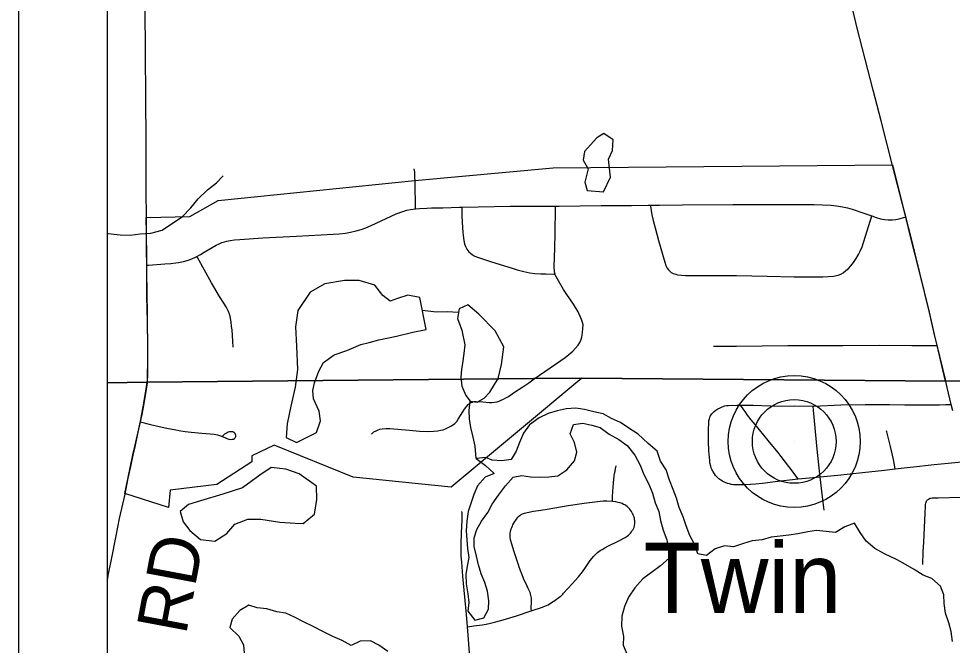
# Model space of a CAD drawing. Extents: x 0 to 34, y 0 to 22.
# Drawn here: x 2.014 to 3.067, y 16.909 to 17.616 of the extents above; entities that cross this region are included whole.
import ezdxf

# ---------------------------------------------------------------- set-up
doc = ezdxf.new("R2010")
doc.units = 0
for name, color, linetype in [('GM_X_City_Street', 7, 'Continuous'), ('GM_X_Corporation', 7, 'Continuous'), ('GM_X_County_Road', 7, 'Continuous'), ('GM_X_County_Road_Text', 7, 'Continuous'), ('GM_X_Minor_Lake', 7, 'Continuous'), ('GM_X_Minor_River', 7, 'Continuous'), ('GM_X_State_Route', 7, 'Continuous'), ('GM_X_Township_Road', 7, 'Continuous'), ('GM_X_Unincorporated', 7, 'Continuous'), ('GM_X_Unincorporated_Location', 7, 'Continuous'), ('GM_X_Unincorporated_Text', 7, 'Continuous'), ('SH_Data', 7, 'Continuous')]:
    doc.layers.add(name, color=color, linetype=linetype)

msp = doc.modelspace()

# ---------------------------------------------------------------- linework, layer by layer
at = {"layer": 'GM_X_City_Street'}
for points in [[(2.1583, 17.3906), (2.158, 17.4222), (2.1578, 17.4806), (2.1575, 17.5236), (2.1571, 17.58), (2.1566, 17.6247)], [(2.4612, 17.4325), (2.461, 17.4364), (2.4608, 17.4426), (2.4603, 17.4464)], [(2.4617, 17.4012), (2.4616, 17.4084), (2.4616, 17.4144), (2.4615, 17.4185), (2.4614, 17.422), (2.4612, 17.4325)], [(2.1588, 17.3375), (2.1604, 17.3376), (2.1791, 17.339), (2.1857, 17.3396), (2.1912, 17.3402), (2.1943, 17.3407), (2.1999, 17.3418), (2.204, 17.3428), (2.2076, 17.344), (2.2126, 17.3461), (2.215, 17.3474), (2.2192, 17.3496), (2.2232, 17.3521), (2.237, 17.3601), (2.2404, 17.3618), (2.2433, 17.363), (2.2462, 17.3639), (2.249, 17.3646), (2.2528, 17.3653), (2.2576, 17.3661), (2.2637, 17.3667), (2.2896, 17.3685), (2.3275, 17.3704), (2.3552, 17.3718), (2.3687, 17.3726), (2.3755, 17.373), (2.3826, 17.3738), (2.3884, 17.3749), (2.3946, 17.3762), (2.4003, 17.3778), (2.4056, 17.3798), (2.4118, 17.3823), (2.4342, 17.3929), (2.44, 17.3954), (2.4473, 17.3983), (2.4518, 17.3997), (2.4562, 17.4005), (2.4617, 17.4012), (2.4663, 17.4016), (2.4743, 17.4019), (2.4799, 17.4022), (2.4926, 17.4024), (2.5112, 17.403), (2.5138, 17.403), (2.5688, 17.404), (2.5891, 17.4042), (2.6198, 17.4041), (2.6239, 17.4041), (2.6711, 17.4048), (2.7052, 17.405), (2.724, 17.4053), (2.7266, 17.4053), (2.7369, 17.4054), (2.763, 17.4058), (2.8195, 17.4061), (2.8617, 17.4062), (2.9114, 17.406), (2.9208, 17.4057), (2.9306, 17.4051), (2.9366, 17.4044), (2.9434, 17.4034), (2.949, 17.4022), (2.9542, 17.4008), (2.9673, 17.3964), (2.9764, 17.3931), (2.9812, 17.3914), (2.9862, 17.39), (2.9908, 17.3892), (2.9949, 17.3887), (2.9998, 17.3886), (3.0035, 17.3891), (3.0075, 17.3899), (3.0121, 17.3912), (3.0147, 17.3919)], [(2.4122, 17.1469), (2.4148, 17.1495), (2.4172, 17.1509), (2.4196, 17.152), (2.4215, 17.1525), (2.424, 17.1529), (2.4284, 17.1532), (2.4327, 17.1533), (2.4549, 17.1514), (2.4664, 17.1502), (2.4765, 17.1498), (2.4824, 17.1502), (2.4868, 17.1507), (2.4903, 17.1513), (2.493, 17.152), (2.4962, 17.1532), (2.4993, 17.1547), (2.5025, 17.1565), (2.5061, 17.159), (2.5083, 17.1613), (2.51, 17.1638), (2.5124, 17.168), (2.515, 17.1722), (2.517, 17.1752), (2.5195, 17.1787), (2.5211, 17.1803), (2.5231, 17.182), (2.5243, 17.1827), (2.5259, 17.1832), (2.528, 17.1837), (2.5302, 17.1838), (2.5375, 17.1833), (2.5448, 17.1827), (2.5479, 17.1827), (2.5508, 17.183), (2.5539, 17.1836), (2.5562, 17.1843), (2.5585, 17.1853), (2.561, 17.1865), (2.5636, 17.1878), (2.5665, 17.1896), (2.5735, 17.1942), (2.5828, 17.2005), (2.5894, 17.205), (2.5954, 17.2092), (2.6077, 17.2177), (2.6255, 17.23), (2.6305, 17.2336), (2.6345, 17.2367), (2.6392, 17.2407), (2.6422, 17.244), (2.6451, 17.2475), (2.6469, 17.2503), (2.6482, 17.2531), (2.6492, 17.2565), (2.6497, 17.2588), (2.6502, 17.2615), (2.6506, 17.2662), (2.6507, 17.2704), (2.6502, 17.2731), (2.649, 17.2764), (2.6453, 17.2849), (2.6398, 17.2937), (2.6324, 17.3046), (2.6288, 17.3102), (2.6214, 17.3224), (2.6198, 17.3258), (2.6193, 17.3274), (2.6189, 17.3286), (2.6186, 17.3306), (2.6181, 17.3362), (2.6187, 17.3569), (2.6191, 17.3738), (2.6197, 17.4019), (2.6198, 17.4041)], [(2.5138, 17.403), (2.5139, 17.4016), (2.5141, 17.3927), (2.5148, 17.3801), (2.5151, 17.3746), (2.5153, 17.3713), (2.5157, 17.3679), (2.5165, 17.3632), (2.5173, 17.3605), (2.5184, 17.3579), (2.5196, 17.3557), (2.5207, 17.3542), (2.5219, 17.3528), (2.5236, 17.3512), (2.5257, 17.3495), (2.5278, 17.3482), (2.5304, 17.3469), (2.5475, 17.3413), (2.5706, 17.3341), (2.5765, 17.3324), (2.5841, 17.3305), (2.5907, 17.3291), (2.5964, 17.3281), (2.603, 17.3277), (2.6087, 17.3277), (2.6177, 17.3275), (2.6193, 17.3274)], [(2.7266, 17.4053), (2.7268, 17.404), (2.7284, 17.3942), (2.7299, 17.3879), (2.7319, 17.3797), (2.7358, 17.3654), (2.7428, 17.3408), (2.7441, 17.3373), (2.7457, 17.3344), (2.747, 17.3325), (2.7486, 17.3309), (2.7503, 17.3295), (2.7524, 17.3283), (2.7553, 17.3273), (2.7574, 17.3268), (2.7616, 17.3262), (2.7663, 17.3259), (2.7721, 17.3258), (2.7982, 17.326), (2.8237, 17.3258), (2.8585, 17.3252), (2.889, 17.3246), (2.9213, 17.3244), (2.9332, 17.3252), (2.9384, 17.3264), (2.9415, 17.3275), (2.944, 17.3291), (2.9471, 17.3314), (2.95, 17.3339), (2.9528, 17.3367), (2.9559, 17.3405), (2.959, 17.3451), (2.9615, 17.3496), (2.9634, 17.3535), (2.9655, 17.3581), (2.9764, 17.3931)], [(2.1588, 17.3375), (2.1585, 17.3543), (2.1584, 17.3659), (2.1584, 17.3739), (2.1583, 17.3906)], [(2.2559, 17.2452), (2.2555, 17.2517), (2.2547, 17.2647), (2.2543, 17.2684), (2.2538, 17.2737), (2.2531, 17.2776), (2.2525, 17.28), (2.2517, 17.2825), (2.2507, 17.2852), (2.2495, 17.2877), (2.248, 17.2906), (2.2456, 17.2946), (2.2406, 17.3024), (2.2314, 17.3175), (2.2157, 17.3462), (2.215, 17.3474)], [(2.7978, 17.2463), (2.8009, 17.2462), (2.8239, 17.2463), (2.8817, 17.2468), (2.8954, 17.2468), (2.9438, 17.247), (2.9848, 17.2472), (3.0215, 17.2468), (3.0463, 17.2468), (3.0501, 17.2468)], [(2.1515, 17.1609), (2.1527, 17.1606), (2.1613, 17.1583), (2.169, 17.1564), (2.1813, 17.1537), (2.1915, 17.1517), (2.197, 17.1507), (2.202, 17.1498), (2.2085, 17.1492), (2.2208, 17.1482), (2.2345, 17.1468), (2.2384, 17.1462), (2.2419, 17.1451), (2.2467, 17.1432), (2.2489, 17.1422), (2.251, 17.1415), (2.2531, 17.1411), (2.255, 17.1412), (2.2564, 17.1415), (2.2575, 17.142), (2.2583, 17.1428), (2.2588, 17.1435), (2.259, 17.1444), (2.2591, 17.1454), (2.2588, 17.1467), (2.2582, 17.1477), (2.2574, 17.1485), (2.2567, 17.149), (2.2558, 17.1494), (2.2547, 17.1496), (2.2535, 17.1497), (2.2517, 17.1494), (2.2504, 17.1491), (2.2491, 17.1485), (2.2478, 17.1477), (2.2463, 17.1468), (2.2454, 17.1461), (2.244, 17.1446)]]:
    msp.add_lwpolyline(points, dxfattribs=at)
at = {"layer": 'GM_X_Corporation'}
for points in [[(2.114, 20.6173), (2.114, 17.2048), (2.159, 17.2055), (2.1592, 17.2079), (2.1594, 17.2136), (2.1597, 17.2285), (2.1597, 17.2459), (2.1592, 17.275), (2.159, 17.2867), (2.1588, 17.3028), (2.1586, 17.335), (2.1586, 17.338), (2.1583, 17.3549), (2.1582, 17.3665), (2.1582, 17.3745), (2.158, 17.3912), (2.2073, 17.3925), (2.239, 17.4107), (2.461, 17.4331), (2.6171, 17.4475), (2.9997, 17.4506), (3.0109, 17.4069), (3.0145, 17.3925), (3.015, 17.3908), (3.0201, 17.3703), (3.0303, 17.3291), (3.0412, 17.2846), (3.047, 17.2594), (3.0499, 17.2474), (3.0592, 17.2087), (3.0597, 17.2067), (3.4848, 17.2088)], [(2.114, 20.6173), (2.114, 17.2048), (2.159, 17.2055), (2.5952, 17.2097), (2.6493, 17.2102), (3.0597, 17.2067), (3.4848, 17.2088), (3.5941, 17.2097), (3.7259, 17.2107), (4.732, 17.2135)], [(4.732, 17.2135), (3.7259, 17.2107), (3.5941, 17.2097), (3.4848, 17.2088), (3.0597, 17.2067), (2.6493, 17.2102), (2.5952, 17.2097), (2.159, 17.2055), (2.114, 17.2048), (2.114, 13.8173), (5.0539, 13.8173)]]:
    msp.add_lwpolyline(points, dxfattribs=at)
msp.add_lwpolyline([(2.1586, 17.338), (2.1583, 17.3549), (2.1582, 17.3665), (2.1582, 17.3745), (2.158, 17.3912), (2.2073, 17.3925), (2.239, 17.4107), (2.461, 17.4331), (2.6171, 17.4475), (2.9997, 17.4506), (3.0109, 17.4069), (3.0145, 17.3925), (3.015, 17.3908), (3.0201, 17.3703), (3.0303, 17.3291), (3.0412, 17.2846), (3.047, 17.2594), (3.0499, 17.2474), (3.0592, 17.2087), (3.0597, 17.2067), (2.6493, 17.2102), (2.5021, 17.0872), (2.3912, 17.0986), (2.3021, 17.1347), (2.277, 17.1225), (2.277, 17.1159), (2.2376, 17.0903), (2.185, 17.0839), (2.1829, 17.0643), (2.1338, 17.0799), (2.1375, 17.0979), (2.1402, 17.1109), (2.143, 17.1238), (2.1451, 17.1331), (2.1488, 17.1496), (2.1513, 17.1615), (2.153, 17.1697), (2.1553, 17.182), (2.1572, 17.1934), (2.1578, 17.1977), (2.159, 17.2055), (2.1592, 17.2079), (2.1594, 17.2136), (2.1597, 17.2285), (2.1597, 17.2459), (2.1592, 17.275), (2.159, 17.2867), (2.1588, 17.3028), (2.1586, 17.335)], close=True, dxfattribs=at)
at = {"layer": 'GM_X_County_Road'}
for points in [[(2.1592, 17.2049), (2.1594, 17.2074), (2.1597, 17.213), (2.1599, 17.2279), (2.1599, 17.2453), (2.1594, 17.2744), (2.1592, 17.2862), (2.159, 17.3023), (2.1588, 17.3345), (2.1588, 17.3375)], [(2.1515, 17.1609), (2.1532, 17.1692), (2.1555, 17.1814), (2.1574, 17.1929), (2.1581, 17.1972), (2.1592, 17.2049)], [(2.134, 17.0793), (2.1377, 17.0973), (2.1404, 17.1103), (2.1432, 17.1232), (2.1453, 17.1325), (2.149, 17.1491), (2.1515, 17.1609)], [(2.114, 16.9814), (2.1142, 16.9822), (2.1151, 16.9877), (2.1161, 16.9932), (2.1188, 17.0056), (2.1242, 17.0323), (2.1279, 17.052), (2.134, 17.0793)]]:
    msp.add_lwpolyline(points, dxfattribs=at)
at = {"layer": 'GM_X_Minor_Lake'}
for p, q in [((2.6661, 17.4811), (2.6522, 17.4659)), ((2.4736, 17.265), (2.4665, 17.3013)), ((2.5162, 17.2379), (2.5147, 17.227)), ((2.2871, 17.0512), (2.3087, 17.0478))]:
    msp.add_line(p, q, dxfattribs=at)
for points in [[(2.6522, 17.4659), (2.6507, 17.456), (2.6565, 17.4462), (2.6528, 17.4313), (2.6555, 17.4219), (2.6737, 17.4205), (2.6815, 17.4369), (2.6795, 17.4573), (2.684, 17.4669), (2.6846, 17.479), (2.674, 17.4861), (2.6661, 17.4811)], [(2.4665, 17.3013), (2.4532, 17.3039), (2.4415, 17.3), (2.4332, 17.2969), (2.4248, 17.3033), (2.4157, 17.315), (2.3982, 17.3202), (2.3815, 17.3204), (2.3596, 17.3164), (2.343, 17.3072), (2.3288, 17.2866), (2.3263, 17.268), (2.3276, 17.2464), (2.3286, 17.2199), (2.3261, 17.2001), (2.321, 17.1785), (2.317, 17.1587), (2.3159, 17.1432), (2.3273, 17.1376), (2.35, 17.1487), (2.3544, 17.1621), (2.3532, 17.173), (2.3466, 17.187), (2.3458, 17.1961), (2.3476, 17.2049), (2.3528, 17.2182), (2.358, 17.2277), (2.3701, 17.2365), (2.3844, 17.2415), (2.3999, 17.2481), (2.4093, 17.2505), (2.4203, 17.2532), (2.4403, 17.2575), (2.4588, 17.2622), (2.4736, 17.265)], [(2.5147, 17.227), (2.5137, 17.2198), (2.513, 17.2111), (2.5138, 17.2012), (2.5184, 17.1906), (2.5234, 17.1842), (2.5314, 17.1831), (2.5393, 17.1874), (2.5457, 17.1942), (2.555, 17.2099), (2.5587, 17.2254), (2.5615, 17.2456), (2.5516, 17.2637), (2.5332, 17.2825), (2.5207, 17.2927), (2.5109, 17.2884), (2.5091, 17.2774), (2.5141, 17.2642), (2.5172, 17.2479), (2.5162, 17.2379)], [(3.0659, 16.9245), (3.0632, 16.9343), (3.0597, 16.9449), (3.0581, 16.9559), (3.0576, 16.9657), (3.0541, 16.9756), (3.0442, 16.9842), (3.0344, 16.9879), (3.0241, 16.9943), (3.0146, 16.9999), (3.0051, 17.0052), (2.9907, 17.0119), (2.98, 17.0179), (2.9701, 17.0261), (2.9632, 17.0359), (2.9571, 17.0465), (2.9461, 17.0426), (2.9356, 17.0361), (2.925, 17.0372), (2.914, 17.0382), (2.9042, 17.0366), (2.8932, 17.0346), (2.883, 17.033), (2.8732, 17.0318), (2.863, 17.0306), (2.8528, 17.0279), (2.8414, 17.0266), (2.8316, 17.0235), (2.8203, 17.02), (2.8104, 17.0211), (2.7999, 17.0176), (2.7901, 17.0099), (2.7802, 17.0118), (2.7763, 17.0227), (2.771, 17.0325), (2.7671, 17.0435), (2.7636, 17.0537), (2.759, 17.0643), (2.7563, 17.0749), (2.7524, 17.0847), (2.7482, 17.0949), (2.7443, 17.1067), (2.7382, 17.1165), (2.7343, 17.1278), (2.724, 17.1365), (2.7129, 17.147), (2.7023, 17.1537), (2.6928, 17.1601), (2.6829, 17.1646), (2.6734, 17.1698), (2.6628, 17.172), (2.6525, 17.1746), (2.6427, 17.1764), (2.6317, 17.1756), (2.6215, 17.1732), (2.6113, 17.1701), (2.6011, 17.1655), (2.5902, 17.1574), (2.5835, 17.1479), (2.579, 17.1376), (2.5753, 17.1277), (2.5697, 17.1182), (2.5591, 17.117), (2.5481, 17.1177), (2.5411, 17.1208), (2.53, 17.1194), (2.5406, 17.1115), (2.5505, 17.1025), (2.5403, 17.0983), (2.5317, 17.0887), (2.5276, 17.0788), (2.521, 17.0598), (2.5195, 17.0488), (2.5189, 17.0378), (2.5197, 17.0276), (2.5202, 17.0181), (2.5217, 17.0079), (2.5199, 16.998), (2.5185, 16.9885), (2.519, 16.9783), (2.5209, 16.9669), (2.5218, 16.957), (2.5207, 16.9472), (2.5287, 16.937), (2.5389, 16.9397), (2.5442, 16.9496), (2.5445, 16.9591), (2.5429, 16.9697), (2.5398, 16.9796), (2.5359, 16.9894), (2.5328, 16.9996), (2.5304, 17.0094), (2.5277, 17.0204), (2.528, 17.0299), (2.531, 17.0394), (2.5362, 17.0489), (2.5433, 17.0585), (2.5482, 17.068), (2.5553, 17.0783), (2.5631, 17.0886), (2.5718, 17.0985)], [(2.5718, 17.0985), (2.5816, 17.1005), (2.5914, 17.099), (2.6024, 17.0984), (2.6123, 17.0988), (2.6221, 17.1), (2.6326, 17.1066), (2.6409, 17.1169), (2.6438, 17.1267), (2.6411, 17.1377), (2.6361, 17.1475), (2.6398, 17.1578), (2.6504, 17.1594), (2.6606, 17.1572), (2.6701, 17.1543), (2.68, 17.1471), (2.691, 17.1411), (2.7005, 17.134), (2.7093, 17.1231), (2.7151, 17.1121), (2.7193, 17.1015), (2.7251, 17.0906), (2.729, 17.0804), (2.7321, 17.0694), (2.7363, 17.0596), (2.7379, 17.0494), (2.741, 17.0388), (2.7453, 17.0278), (2.7473, 17.0164), (2.7477, 17.007), (2.7379, 16.9985), (2.7278, 16.9909), (2.718, 16.9836), (2.709, 16.9737), (2.7019, 16.963), (2.6974, 16.9527), (2.6945, 16.9417), (2.6942, 16.9303), (2.6962, 16.9186), (2.6959, 16.9091), (2.7009, 16.8974)], [(2.3087, 17.0478), (2.3258, 17.0465), (2.3349, 17.0462), (2.3476, 17.0566), (2.3505, 17.0733), (2.35, 17.0884), (2.3306, 17.1023), (2.3155, 17.1075), (2.2988, 17.1093), (2.286, 17.1008), (2.2664, 17.0863), (2.2445, 17.0793), (2.2192, 17.0719), (2.2056, 17.0676), (2.1962, 17.0596), (2.1997, 17.0482), (2.207, 17.0384), (2.2192, 17.0283), (2.2355, 17.0261), (2.2487, 17.035), (2.258, 17.0453), (2.2724, 17.0511), (2.2871, 17.0512)], [(2.4306, 16.9017), (2.4203, 16.9089), (2.4108, 16.9137), (2.3991, 16.9136), (2.3893, 16.9086), (2.379, 16.9142), (2.3684, 16.9187), (2.3578, 16.9239), (2.3464, 16.9299), (2.3353, 16.9351), (2.3251, 16.9407), (2.3156, 16.9452), (2.3054, 16.9467), (2.294, 16.95), (2.283, 16.951), (2.2735, 16.954), (2.2637, 16.9482), (2.2547, 16.9383), (2.2521, 16.9288), (2.2624, 16.919), (2.2678, 16.9092), (2.2695, 16.8865)], [(3.0675, 16.9131), (3.0659, 16.9245)]]:
    msp.add_lwpolyline(points, dxfattribs=at)
at = {"layer": 'GM_X_Minor_River'}
for points in [[(2.114, 17.3733), (2.1151, 17.3733), (2.1287, 17.3719), (2.1397, 17.3716), (2.151, 17.3729), (2.1631, 17.3737), (2.176, 17.3772), (2.1876, 17.3849), (2.1986, 17.3922), (2.2083, 17.4021), (2.2166, 17.4124), (2.2271, 17.4227), (2.2373, 17.4304), (2.2448, 17.4384)], [(2.5101, 17.2841), (2.4976, 17.2849), (2.4855, 17.2844), (2.4694, 17.2865)], [(2.53, 17.1194), (2.5291, 17.1334), (2.5267, 17.1437), (2.524, 17.1543), (2.5228, 17.1641), (2.5223, 17.1736), (2.5234, 17.1842)]]:
    msp.add_lwpolyline(points, dxfattribs=at)
at = {"layer": 'GM_X_State_Route'}
for points in [[(2.9999, 17.4501), (2.987, 17.5006), (2.978, 17.5352), (2.9599, 17.605), (2.9549, 17.6255), (2.9455, 17.6635), (2.9391, 17.6887), (2.9283, 17.7309), (2.9091, 17.8068), (2.8922, 17.8738), (2.8906, 17.8802), (2.8901, 17.8821)], [(3.0596, 17.2072), (3.0594, 17.2082), (3.0501, 17.2468), (3.0472, 17.2589), (3.0414, 17.2841), (3.0306, 17.3286), (3.0203, 17.3698), (3.0152, 17.3903), (3.0147, 17.3919), (3.0111, 17.4063), (2.9999, 17.4501)], [(3.0677, 17.1731), (3.066, 17.1805), (3.0615, 17.1997), (3.0599, 17.2062), (3.0596, 17.2072)]]:
    msp.add_lwpolyline(points, dxfattribs=at)
at = {"layer": 'GM_X_Township_Road'}
msp.add_line((2.8935, 17.0965), (2.9183, 17.0989), dxfattribs=at)
for points in [[(2.7971, 17.1712), (2.7988, 17.1726), (2.8005, 17.174), (2.8029, 17.1755), (2.8054, 17.1768), (2.8078, 17.1777), (2.8105, 17.1788), (2.8126, 17.1792), (2.8147, 17.1793), (2.8242, 17.1797), (2.8284, 17.1797)], [(2.8284, 17.1797), (2.8427, 17.1798), (2.8624, 17.1789), (2.8751, 17.1787), (2.8893, 17.1788), (2.9103, 17.1787)], [(2.8935, 17.0965), (2.8828, 17.1104), (2.8704, 17.1266), (2.8594, 17.1399), (2.8447, 17.1578), (2.8405, 17.1631), (2.8363, 17.1685), (2.8342, 17.1715), (2.8284, 17.1797)], [(2.9103, 17.1787), (2.9112, 17.1787), (2.9415, 17.18), (2.9688, 17.1804), (2.9965, 17.1804), (3.0137, 17.1799), (3.0348, 17.1799), (3.0528, 17.1801), (3.0596, 17.1803), (3.066, 17.1805)], [(2.9183, 17.0989), (2.918, 17.1019), (2.915, 17.1302), (2.9107, 17.1741), (2.9103, 17.1787)], [(2.8082, 17.0939), (2.806, 17.0951), (2.804, 17.0965), (2.8017, 17.0987), (2.8003, 17.1005), (2.7991, 17.1021), (2.797, 17.1053), (2.7957, 17.108), (2.7947, 17.111), (2.7939, 17.1146), (2.7936, 17.1176), (2.7932, 17.1208), (2.7927, 17.1283), (2.7924, 17.1389), (2.7923, 17.1519), (2.7927, 17.16), (2.7928, 17.1622), (2.7932, 17.1644), (2.7936, 17.1658), (2.7942, 17.1672), (2.7951, 17.1687), (2.7961, 17.17), (2.7971, 17.1712)], [(3.0029, 17.1079), (3.0018, 17.1143), (3.0011, 17.1185), (2.9977, 17.1331), (2.9935, 17.1496), (2.9929, 17.1507)], [(3.0029, 17.1079), (3.0128, 17.109), (3.0302, 17.1108), (3.0368, 17.1116), (3.0468, 17.1128), (3.0626, 17.1144), (3.074, 17.1155), (3.0803, 17.1162)], [(2.6839, 17.0709), (2.684, 17.0745), (2.6841, 17.0777), (2.6843, 17.0806), (2.6845, 17.0828), (2.6851, 17.0916), (2.6852, 17.0932), (2.6854, 17.095), (2.6855, 17.097), (2.6857, 17.0989), (2.6859, 17.1005), (2.6863, 17.1026), (2.6868, 17.1052), (2.6873, 17.1079), (2.6879, 17.1111)], [(2.9183, 17.0989), (2.9382, 17.1008), (2.966, 17.1038), (2.9906, 17.1064), (3.0029, 17.1079)], [(2.8082, 17.0939), (2.8107, 17.0929), (2.8132, 17.0918), (2.8157, 17.0912), (2.8177, 17.0907), (2.8204, 17.0902), (2.8254, 17.09), (2.829, 17.09), (2.8341, 17.0901), (2.8395, 17.0905), (2.8451, 17.0909), (2.853, 17.0918), (2.8674, 17.0935), (2.8935, 17.0965)], [(2.9227, 17.0614), (2.921, 17.0762), (2.9183, 17.0989)], [(3.034, 16.9998), (3.0344, 17.0141), (3.0351, 17.0252), (3.0365, 17.058), (3.037, 17.0654), (3.0372, 17.0677), (3.0374, 17.069), (3.0377, 17.0702), (3.0381, 17.0714), (3.0387, 17.0723), (3.0392, 17.0729), (3.0399, 17.0734), (3.0406, 17.0738)], [(3.0406, 17.0738), (3.0416, 17.0743), (3.0424, 17.0746), (3.0432, 17.0748), (3.0444, 17.075), (3.0458, 17.0751), (3.0514, 17.0753), (3.0764, 17.0758), (3.0854, 17.076)], [(2.5203, 16.9297), (2.5274, 16.9307), (2.5368, 16.9319), (2.5415, 16.9328), (2.5463, 16.9337), (2.5495, 16.9345), (2.5523, 16.9352), (2.5563, 16.9363), (2.5607, 16.9375), (2.5755, 16.9422), (2.5922, 16.9476), (2.605, 16.9519), (2.6083, 16.9534), (2.6112, 16.9546), (2.6129, 16.9556), (2.6149, 16.9567), (2.6164, 16.9577), (2.6179, 16.9587), (2.6249, 16.9638), (2.6256, 16.9643), (2.6267, 16.9653), (2.6279, 16.9666), (2.6287, 16.9675), (2.6385, 16.9782), (2.6455, 16.9859), (2.65, 16.9916), (2.6536, 16.9966), (2.6589, 17.0043), (2.661, 17.007), (2.6624, 17.0088), (2.664, 17.0104), (2.6655, 17.012), (2.667, 17.0134), (2.6684, 17.0145), (2.6702, 17.0158), (2.6721, 17.017), (2.6752, 17.0187), (2.6787, 17.0206), (2.6904, 17.0263), (2.6981, 17.0303), (2.7006, 17.0319), (2.7019, 17.0331), (2.7032, 17.0343), (2.7042, 17.0354), (2.7052, 17.0366), (2.7063, 17.0382), (2.7072, 17.0396), (2.7082, 17.0417), (2.7088, 17.0439), (2.7092, 17.0462), (2.7092, 17.0477), (2.7091, 17.0491), (2.7089, 17.0505), (2.7086, 17.0521), (2.7082, 17.0535), (2.7078, 17.0549), (2.7071, 17.0564), (2.7065, 17.0576), (2.7053, 17.0596), (2.7043, 17.0612), (2.7034, 17.0624), (2.7024, 17.0636), (2.7014, 17.0647), (2.7003, 17.0655), (2.699, 17.0664), (2.6977, 17.0671), (2.6963, 17.0678), (2.6947, 17.0686), (2.6926, 17.0694), (2.6904, 17.0699), (2.6876, 17.0705), (2.6839, 17.0709)], [(2.6839, 17.0709), (2.6776, 17.0712), (2.6753, 17.0712), (2.6733, 17.0712), (2.6701, 17.071), (2.6672, 17.0707), (2.6519, 17.0686), (2.6341, 17.066), (2.6101, 17.0619), (2.603, 17.0609), (2.595, 17.0599), (2.5842, 17.0576), (2.5819, 17.0567), (2.5806, 17.0559), (2.5793, 17.055), (2.5781, 17.054), (2.5764, 17.0524), (2.5754, 17.0512), (2.5744, 17.05), (2.5734, 17.0483), (2.5723, 17.0466), (2.5713, 17.0447), (2.5706, 17.043), (2.57, 17.0414), (2.5694, 17.0398), (2.5686, 17.0373), (2.5682, 17.0352), (2.568, 17.033), (2.568, 17.0303), (2.5685, 17.028), (2.5702, 17.0223), (2.5724, 17.0156), (2.5774, 17), (2.5784, 16.9974), (2.5791, 16.9953), (2.5799, 16.9932), (2.5805, 16.9917), (2.5833, 16.9847), (2.5874, 16.9759), (2.5885, 16.9734), (2.5897, 16.9708), (2.5905, 16.9687), (2.5912, 16.9667), (2.5916, 16.9651), (2.5919, 16.9636), (2.5921, 16.9619), (2.5922, 16.9604), (2.5922, 16.9589), (2.5921, 16.9572), (2.592, 16.9554), (2.5917, 16.9531), (2.5918, 16.9502), (2.5922, 16.9476)], [(2.5203, 16.9297), (2.5192, 16.9434), (2.515, 16.9866), (2.5138, 17.0026), (2.5134, 17.0094), (2.5131, 17.0144), (2.5131, 17.0192), (2.5131, 17.0231), (2.5136, 17.0356), (2.5144, 17.0498), (2.5144, 17.0516), (2.5144, 17.0538), (2.5144, 17.056), (2.5142, 17.0578), (2.5141, 17.0596)], [(2.5226, 16.9003), (2.521, 16.9201), (2.5203, 16.9297)]]:
    msp.add_lwpolyline(points, dxfattribs=at)
at = {"layer": 'GM_X_Unincorporated'}
for radius in [0.0744, 0.0472]:
    msp.add_circle((2.889, 17.1387), radius, dxfattribs=at)
at = {"layer": 'GM_X_Unincorporated_Location'}
msp.add_line((2.889, 17.1387), (2.889, 17.1387), dxfattribs=at)
at = {"layer": 'SH_Data'}
for p, q in [((2.014, 20.7173), (2.014, 13.7173)), ((2.114, 20.6173), (2.114, 13.8173))]:
    msp.add_line(p, q, dxfattribs=at)

# ---------------------------------------------------------------- texts
at = {"layer": 'GM_X_County_Road_Text'}
msp.add_text('RD', height=0.05682, rotation=79.3244, dxfattribs=at).set_placement((2.2027, 16.9194))
at = {"layer": 'GM_X_Unincorporated_Text'}
msp.add_text('Twin', height=0.07898, rotation=0, dxfattribs=at).set_placement((2.7191, 16.9454))

doc.saveas('drawing.dxf')
